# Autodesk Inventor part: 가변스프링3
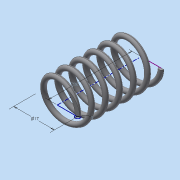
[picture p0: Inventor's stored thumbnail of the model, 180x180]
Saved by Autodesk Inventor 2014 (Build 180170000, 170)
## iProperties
Created: 2023-01
Part Number: 가변스프링3
Material: 일반
Document SubType Name: Modeling
Designer: dg
Density: 1 g/cm^3
Appearance: 기본값
Author: dg
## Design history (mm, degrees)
sketch "스케치1"
  geometry: L1 (8.5, 0)-(0, 0); L2 (0, 0)-(0, 35); L3 (0, 35)-(8.5, 35); C1 r 1 at (8.5, 0)
  constraints: 6 end point, 1 centre point, 1 coincident, 1 horizontal, 1 parallel, 1 perpendicular, 1 vertical alignment
  dimensions: "d0" = 17 diameter of L1.start L2; "d1" = 35 distance of L1.end L2.end (derived); "d2" = 2 diameter of C1
feature "코일1" pitch "d3" = 10; turns "d5" = 6; dims "d4" = 35 (= d1), "d6" = 0, angle "d7" = 90 deg, angle "d8" = 90 deg, "d9" = 0, "d10" = 0
node "작업 평면1"
node "작업 평면2"
feature "분할1"
feature "분할2"
node "솔리드1"
other parameters: "d11" = 90 deg, "d12" = 90 deg
